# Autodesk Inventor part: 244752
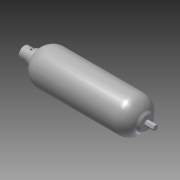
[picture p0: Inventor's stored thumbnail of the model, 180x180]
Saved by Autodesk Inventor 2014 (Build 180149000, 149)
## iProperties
Shininess: 20.0
Length Units: 11272
Angle Units: 11279
Time Units: 11290
Mass Units: 11286
Length Display Precision: 3
Angle Display Precision: 2
Company: Autodesk, Inc.
Created: 2002-07
Part Number: 244752
Material: Stainless Steel, 440C
Description: ACCUMULATOR
Document SubType Name: Modeling
Designer: Autodesk, Inc.
Density: 7.75 g/cm^3
Mass: 72473.7 g
Surface Area: 9848.93 cm^2
Volume: 9351.44 cm^3
Appearance: Steel
Density: 0.0
Volumn: 0.0
Area: 0.0
PropertySet Name: Model Information
Control State: 0
Master: False
Checked Out: False
Last Check In By: JT
Last Check In Date: 2003-06-20
Title: ACCUMULATOR
Author: Autodesk, Inc.
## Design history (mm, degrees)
sketch "Sketch1"
  geometry: L1 (0, 0)-(-438.15, 0); L2 (0, 0)-(361.95, 0); L3 (361.95, 0)-(361.95, 44.45); L4 (361.95, 44.45)-(349.25, 57.15); L5 (257.889, 114.3)-(-257.889, 114.3); L6 (-349.25, 57.15)-(-349.25, 47.625); L7 (-349.25, 47.625)-(-379.412, 47.625); L8 (-379.412, 47.625)-(-379.412, 38.1); L9 (-379.412, 38.1)-(-438.15, 38.1); L10 (-438.15, 38.1)-(-438.15, 0); L11 (0, 114.3)-(0, 0); L12 (361.95, 0)-(-438.15, 0); L13 (-419.1, 0)-(-419.1, 19.05); L14 (-419.1, 19.05)-(-360.362, 19.05); L15 (-360.362, 19.05)-(-360.362, 28.575); L16 (-360.362, 28.575)-(-330.2, 28.575); L17 (-330.2, 28.575)-(-330.2, 52.521); L18 (-257.889, 95.25)-(257.889, 95.25); L19 (335.403, 41.091)-(335.403, 0); L20 (-419.1, 0)-(335.403, 0); A1 r 101.6 centre (257.889, 12.7) between (349.25, 57.15) and (257.889, 114.3); A2 r 101.6 centre (-257.889, 12.7) between (-257.889, 114.3) and (-349.25, 57.15); A3 r 82.55 centre (-257.889, 12.7) between (-257.889, 95.25) and (-330.2, 52.521); A4 r 82.55 centre (257.889, 12.7) between (335.403, 41.091) and (257.889, 95.25)
  constraints: 40 end point, 8 point on circle, 6 parallel, 4 centre point, 3 collinear, 2 tangent, 1 horizontal, 1 horizontal alignment, 1 midpoint, 1 perpendicular, 1 point on line, 1 vertical, 7 other
  dimensions: "d3" = 228.6 diameter of L5 L1; "d4" = 698.5 distance from line of L6 L4.end; "d5" = 114.3 diameter of L4.end L2; "d6" = 88.9 diameter of L3.end L2; "d7" = 12.7 distance from line of L4.end L3; "d8" = 114.3 diameter of L6.start L1; "d9" = 95.25 diameter of L7 L1; "d10" = 76.2 diameter of L9 L1; "d11" = 30.1625 distance of L6.end L7.end; "d12" = 58.7375 distance of L8.end L9.end; "d13" = 101.6 radius of A2; "d35" = 19.05 distance between parallel lines of L18 L5
revolve "Revolution1" sketch "Sketch1" stored, may be unused: angle "d15" = 90 deg
sketch "Sketch2"
  geometry: L1 (8.249, 14.287)-(16.498, 0); L2 (16.498, 0)-(8.249, -14.287); L3 (8.249, -14.287)-(-8.249, -14.287); L4 (-8.249, -14.287)-(-16.498, 0); L5 (-16.498, 0)-(-8.249, 14.287); L6 (-8.249, 14.287)-(8.249, 14.287); C1 r 44.45 at (0, 0) reference; 1 further point
  constraints: 12 end point, 1 coincident, 1 horizontal, 11 other
  dimensions: "d16" = 28.575 distance between parallel lines of L6 L3
extrude "Extrusion2" join sketch "Sketch2" distance "d17" = 57.15; taper "d18" = 0 deg
sketch "Sketch3"
  geometry: L1 (438.15, 38.1)-(438.15, -38.1) reference; L2 (438.15, 24.663)-(434.975, 23.812); L3 (434.975, 23.812)-(415.138, 23.812); L4 (415.138, 23.812)-(410.375, 19.05); L5 (410.375, 19.05)-(358.924, 19.05); L6 (358.924, 19.05)-(343.16, 0); L7 (438.15, 0)-(343.16, 0)
  constraints: 12 end point, 1 horizontal, 1 midpoint, 1 parallel, 1 perpendicular, 1 point on line
  dimensions: "d19" = 38.1 diameter of L5 L7; "d20" = 47.625 diameter of L3 L7; "d21" = 3.175 horizontal distance of L2.start L2.end; "d22" = 23.0124 distance from line of L1 L3.end; "d24" = 15 deg angle of L3 L2; "d25" = 45 deg angle of L5 L4
revolve "Revolution2" sketch "Sketch3" stored, may be unused: angle "d26" = 90 deg
workplane "Work Plane1"
sketch "Sketch4"
  geometry: L1 (-7.569, 37.341)-(-7.144, 35.753); L2 (-7.144, 35.753)-(-7.144, 22.631); L3 (-7.144, 22.631)-(-4.763, 20.25); L4 (-4.763, 20.25)-(-4.763, 16.084); L5 (-4.763, 16.084)-(0, 16.084); L6 (0, 0)-(0, 38.1); L7 (-7.569, 37.341)-(-8.852, 42.13); L8 (-8.852, 42.13)-(0, 42.13); L9 (0, 42.13)-(0, 38.1); A1 r 38.1 centre (0, 0) between (-7.569, 37.341) and (0, 38.1) reference
  constraints: 18 end point, 3 perpendicular, 2 point on circle, 1 collinear, 1 parallel, 1 point on line, 1 vertical
  dimensions: "d28" = 9.525 diameter of L4 L6; "d29" = 14.2875 diameter of L2 L6; "d30" = 15 deg angle of L1 L2; "d31" = 45 deg angle of L2 L3; "d32" = 1.5875 vertical distance of L1.start L1.end; "d33" = 15.4686 vertical distance of L2.end L6.end
revolve "Revolution3" sketch "Sketch4" stored, may be unused: angle "d34" = 90 deg
body "Solid1"
other parameters: "d27" = 12.7
